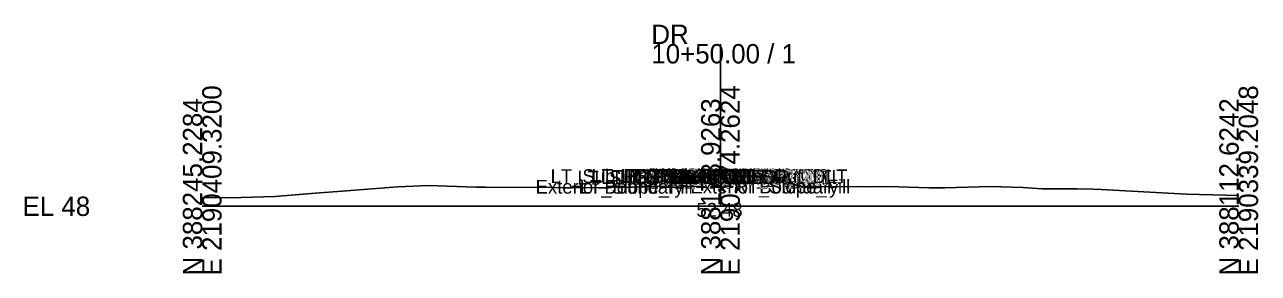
# Model space of a CAD drawing. Extents: x -26 to 153, y 490 to 1524.
# Drawn here: x -25.7 to 152.8, y 490.3 to 526.2 of the extents above; entities that cross this region are included whole.
import ezdxf

# ---------------------------------------------------------------- set-up
doc = ezdxf.new("R2010")
doc.units = 0
for name, color, linetype in [('Default', 7, 'Continuous'), ('Exist CMT Ground Line', 7, 'Continuous'), ('Exist Cross Section Cell', 7, 'Continuous'), ('Exist XS Center Line Elevation Label', 7, 'Continuous'), ('Prop CMT Shld Paved Course 1', 7, 'Continuous'), ('Scratch_Level_1', 7, 'Continuous')]:
    doc.layers.add(name, color=color, linetype=linetype)

msp = doc.modelspace()

# ---------------------------------------------------------------- linework, layer by layer
at = {"layer": 'Exist CMT Ground Line'}
for p, q in [((64.93, 503.09), (67.38, 503.91)), ((67.38, 503.91), (68.35, 504.23)), ((68.35, 504.23), (69.35, 504.31)), ((69.35, 504.31), (69.86, 504.35)), ((69.86, 504.35), (70.35, 504.39)), ((70.35, 504.39), (71.93, 504.42)), ((71.93, 504.42), (75, 504.48)), ((75, 504.48), (78.58, 504.41)), ((78.58, 504.41), (80.42, 504.38)), ((80.42, 504.38), (80.91, 504.34)), ((80.91, 504.34), (81.91, 504.26)), ((81.91, 504.26), (82.42, 504.22)), ((82.42, 504.22), (83.72, 503.78)), ((83.72, 503.78), (86.52, 502.85)), ((10.49, 501.4), (16.98, 501.93)), ((16.98, 501.93), (19.63, 502.12)), ((19.63, 502.12), (28.29, 502.81)), ((28.29, 502.81), (32.69, 502.99)), ((32.69, 502.99), (39.6, 502.78)), ((39.6, 502.78), (41.02, 502.78)), ((41.02, 502.78), (50.91, 502.69)), ((50.91, 502.69), (54.89, 502.67)), ((54.89, 502.67), (59.23, 502.73)), ((59.23, 502.73), (64.11, 502.82)), ((64.11, 502.82), (64.93, 503.09)), ((86.52, 502.85), (89.55, 502.85)), ((89.55, 502.85), (96.17, 502.81)), ((96.17, 502.81), (99.29, 502.88)), ((99.29, 502.88), (105.21, 502.64)), ((105.21, 502.64), (106.69, 502.66)), ((106.69, 502.66), (107.48, 502.66)), ((107.48, 502.66), (114.09, 502.87)), ((114.09, 502.87), (118.79, 502.71)), ((118.79, 502.71), (121.49, 502.51)), ((121.49, 502.51), (126.6, 502.52)), ((126.6, 502.52), (128.89, 502.45)), ((128.89, 502.45), (130.1, 502.44)), ((130.1, 502.44), (142.45, 501.76)), ((142.45, 501.76), (148.13, 501.58)), ((0, 501.22), (5.66, 501.28)), ((5.66, 501.28), (10.49, 501.4)), ((148.13, 501.58), (150, 501.56))]:
    msp.add_line(p, q, dxfattribs=at)
at = {"layer": 'Exist Cross Section Cell'}
for p, q in [((75, 500), (75, 523.45)), ((0, 500), (75, 500)), ((75, 500), (150, 500))]:
    msp.add_line(p, q, dxfattribs=at)
at = {"layer": 'Prop CMT Shld Paved Course 1'}
msp.add_lwpolyline([(80.42, 504.38), (80.43, 504.37)], dxfattribs=at)

# ---------------------------------------------------------------- texts
at = {"layer": 'Default'}
msp.add_text('-', height=0.0001, dxfattribs=at).set_placement((0, 500))
at = {"layer": 'Exist Cross Section Cell'}
for s, p in [('DR', (65, 523.45)), ('10+50.00 / 1', (65, 520.65)), ('EL 48', (-26, 498.6))]:
    msp.add_text(s, height=2.8, dxfattribs=at).set_placement(p)
for s, p in [('E 2190409.3200', (2.8, 490)), ('E 2190374.2624', (77.8, 490)), ('E 2190339.2048', (152.8, 490)), ('N 388245.2284', (0, 490)), ('N 388178.9263', (75, 490)), ('N 388112.6242', (150, 490))]:
    msp.add_text(s, height=2.8, rotation=90, dxfattribs=at).set_placement(p)
at = {"layer": 'Exist XS Center Line Elevation Label'}
msp.add_text('52.48', height=2, dxfattribs=at).set_placement((71.52, 498.48))
at = {"layer": 'Scratch_Level_1'}
for s, p in [('LT_Sub_Trench_Out_DLT', (50.42, 503.35)), ('LT_PS2_Shelf_Out', (56.32, 503.38)), ('LT_GS_OS_CTL', (57.72, 503.23)), ('LT_PV2_OEOT', (60.52, 503.38)), ('LT_PS2_OEOP', (60.58, 503.38)), ('LT_PV1_OEOT', (61.09, 503.39)), ('RT_Sub_Trench_Out_DLT', (61.43, 503.34)), ('RT_Sub_OEEOP', (64.17, 503.22)), ('LT_Sub_OEEOP', (64.21, 503.22)), ('RT_PV2_OEEOP', (64.26, 503.47)), ('LT_PV2_OEEOP', (64.31, 503.47)), ('RT_PV1_OEEOP', (64.83, 503.36)), ('LT_PV1_OEEOP', (64.87, 503.36)), ('RT_PV2_IEEOP', (64.91, 503.47)), ('LT_PV2_IEEOP', (64.95, 503.47)), ('RT_PV1_IEEOP', (65.47, 503.36)), ('LT_PV1_IEEOP', (65.52, 503.36)), ('RT_PS2_Shelf_Out', (66.37, 503.37)), ('PV2_PGL', (68.91, 503.47)), ('PV1_PGL', (69.47, 503.48)), ('RT_PV2_OEOT', (70.55, 503.37)), ('RT_PS2_OEOP', (70.62, 503.37)), ('RT_PV1_OEOT', (71.11, 503.38)), ('Exterior Boundary', (48.25, 501.82)), ('LT_Sub_Trench_Out', (54.29, 503.13)), ('LT_Slope_Fill', (54.63, 501.82)), ('LT_Sub_OEOT', (60.43, 503.13)), ('RT_Sub_Trench_Out', (64.84, 503.11)), ('RT_Sub_OEOT', (70.45, 503.12)), ('Exterior Boundary', (70.66, 501.85)), ('RT_GS_OS_CTL', (71.74, 503.22)), ('RT_Slope_Fill', (76.99, 501.85))]:
    msp.add_text(s, height=2, dxfattribs=at).set_placement(p)

doc.saveas('drawing.dxf')
